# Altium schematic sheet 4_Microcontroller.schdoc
size 309 x 223 mm; Symbol: Sheet-Symbol_A4; Device: Sheet-Symbol_A4; @Project Name: ODrive Rev Motor Module; @Page Count: 5; @Update Date: 2024-10-23; @Create Date: 2024-10-18; @Schematic Name: Schematic-A; @Page No: 4; @Page Name: Microcontroller; Company: EasyEDA.com; Reviewed: EasyEDA; Version: V0.1; Page Size: A4; Part Number: JLCPCB-002; Drawn: EasyEDA; @Board Name: BaseModule; @Create Time: 18:23:50; @Update Time: 17:08:23
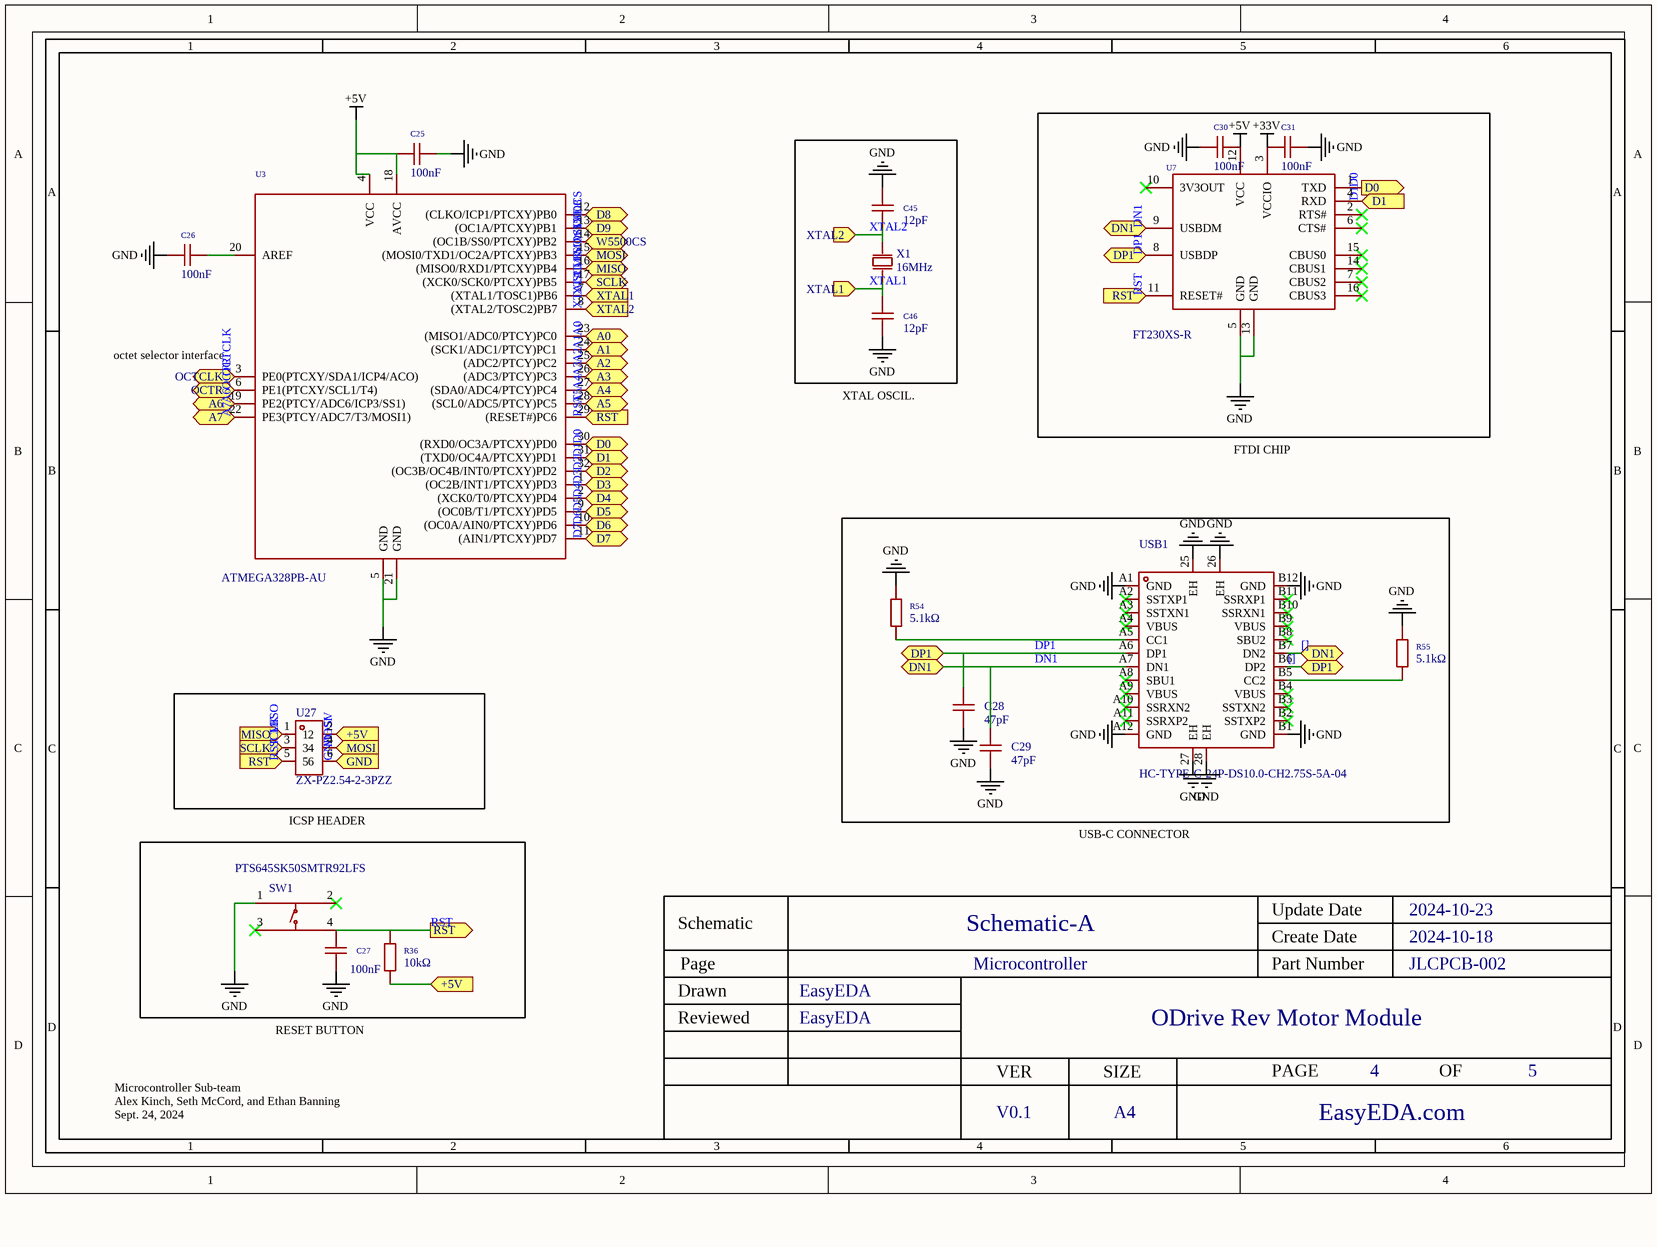
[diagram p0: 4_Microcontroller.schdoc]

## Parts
C25  100nF  [C0805]  (value not drawn)
C26  100nF  [C0805]  (value not drawn)
C27  100nF  [C0805]  (value not drawn)
C28  47pF  [C0805]  (value not drawn)
C29  47pF  [C0805]  (value not drawn)
C30  100nF  [C0805]  (value not drawn)
C31  100nF  [C0805]  (value not drawn)
C45  12pF  [C0402]  (value not drawn)
C46  12pF  [C0402]  (value not drawn)
R36  10kΩ  [R0805]  (value not drawn)
R54  5.1kΩ  [R0402]  (value not drawn)
R55  5.1kΩ  [R0402]  (value not drawn)
SW1  PTS645SK50SMTR92LFS  [KEY-SMD_4P-L6.0-W6.0-P4.50-LS9.0]  (value not drawn)
U3  ATMEGA328PB-AU  [TQFP-32_L7.0-W7.0-P0.80-LS9.0-BL]  (value not drawn)
U7  FT230XS-R  [SSOP-16_L5.0-W4.4-P0.65-LS6.4-BL]  (value not drawn)
U27  ZX-PZ2.54-2-3PZZ  [HDR-TH_6P-P2.54-V-M-R2-C3-S2.54-1]  (value not drawn)
USB1  HC-TYPE-C-24P-DS10.0-CH2.75S-5A-04  [USB-TYPE-C-SMD_HC-TYPE-C-24P-DS10.0-CH2.75S-5A-04]  (value not drawn)
X1  16MHz  [HC-49S_L11.4-W4.8]  (value not drawn)

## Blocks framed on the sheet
ICSP HEADER: C27 R36 SW1

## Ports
+5V (in), A0 (bidir), A1 (bidir), A2 (bidir), A3 (bidir), A4 (bidir), A5 (bidir), A6 (bidir), A7 (bidir), D0 (bidir), D0 (out), D1 (bidir), D1 (in), D2 (bidir), D3 (bidir), D4 (bidir), D5 (bidir), D6 (bidir), D7 (bidir), D8 (bidir), D9 (bidir), DN1 (bidir), DP1 (bidir), GND (in), MISO (bidir), MISO (in), MOSI (bidir), MOSI (in), OCTCLK (bidir), OCTR (bidir), RST (in), RST (out), SCLK (bidir), SCLK (in), W5500CS (bidir), XTAL1 (in), XTAL2 (in)

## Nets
+5V: C25.1 C30.2 R36.1 U3.4(VCC) U3.18(AVCC) U7.12(VCC) U27.2 ; port +5V
+33V: C31.1 U7.3(VCCIO)
GND: C25.2 C26.1 C27.1 C28.1 C29.1 C30.1 C31.2 C45.2 C46.1 R54.2 R55.2 SW1.1 U3.5(GND) U3.21(GND) U7.5(GND) U7.13(GND) U27.6 USB1.25(EH) USB1.26(EH) USB1.27(EH) USB1.28(EH) USB1.A1(GND) USB1.A12(GND) USB1.B1(GND) USB1.B12(GND) ; port GND
[]: C28.2 C29.2 U7.8(USBDP) U7.9(USBDM) USB1.A6(DP1) USB1.A7(DN1) USB1.B6(DP2) USB1.B7(DN2) ; port DN1, port DP1  [also labelled DN1, DP1]
A0: U3.23((MISO1/ADC0/PTCY)PC0) ; port A0
A1: U3.24((SCK1/ADC1/PTCY)PC1) ; port A1
A2: U3.25((ADC2/PTCY)PC2) ; port A2
A3: U3.26((ADC3/PTCY)PC3) ; port A3
A4: U3.27((SDA0/ADC4/PTCY)PC4) ; port A4
A5: U3.28((SCL0/ADC5/PTCY)PC5) ; port A5
A6: U3.19(PE2(PTCY/ADC6/ICP3/SS1)) ; port A6
A7: U3.22(PE3(PTCY/ADC7/T3/MOSI1)) ; port A7
D0: U3.30((RXD0/OC3A/PTCXY)PD0) U7.1(TXD) ; port D0
D1: U3.31((TXD0/OC4A/PTCXY)PD1) U7.4(RXD) ; port D1
D2: U3.32((OC3B/OC4B/INT0/PTCXY)PD2) ; port D2
D3: U3.1((OC2B/INT1/PTCXY)PD3) ; port D3
D4: U3.2((XCK0/T0/PTCXY)PD4) ; port D4
D5: U3.9((OC0B/T1/PTCXY)PD5) ; port D5
D6: U3.10((OC0A/AIN0/PTCXY)PD6) ; port D6
D7: U3.11((AIN1/PTCXY)PD7) ; port D7
D8: U3.12((CLKO/ICP1/PTCXY)PB0) ; port D8
D9: U3.13((OC1A/PTCXY)PB1) ; port D9
MISO: U3.16((MISO0/RXD1/PTCXY)PB4) U27.1 ; port MISO
MOSI: U3.15((MOSI0/TXD1/OC2A/PTCXY)PB3) U27.4 ; port MOSI
OCTCLK: U3.3(PE0(PTCXY/SDA1/ICP4/ACO)) ; port OCTCLK
OCTR: U3.6(PE1(PTCXY/SCL1/T4)) ; port OCTR
RST: C27.2 R36.2 SW1.4 U3.29((RESET#)PC6) U7.11(RESET#) U27.5 ; port RST
SCLK: U3.17((XCK0/SCK0/PTCXY)PB5) U27.3 ; port SCLK
W5500CS: U3.14((OC1B/SS0/PTCXY)PB2) ; port W5500CS
XTAL1: C46.2 U3.7((XTAL1/TOSC1)PB6) X1.1(OSC1) ; port XTAL1
XTAL2: C45.1 U3.8((XTAL2/TOSC2)PB7) X1.2(OSC2) ; port XTAL2
NetC26_2: C26.2 U3.20(AREF)
NetR54_1: R54.1 USB1.A5(CC1)
NetR55_1: R55.1 USB1.B5(CC2)

Not connected (* = marked no-connect by the designer): SW1 2* 3*; U7 2(RTS#)* 6(CTS#)* 7(CBUS2)* 10(3V3OUT)* 14(CBUS1)* 15(CBUS0)* 16(CBUS3)*; USB1 A2(SSTXP1)* A3(SSTXN1)* A4(VBUS)* A8(SBU1)* A9(VBUS)* A10(SSRXN2)* A11(SSRXP2)* B2(SSTXP2)* B3(SSTXN2)* B4(VBUS)* B8(SBU2)* B9(VBUS)* B10(SSRXN1)* B11(SSRXP1)*

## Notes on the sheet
- (near U3) octet selector interface
- XTAL OSCIL.
- FTDI CHIP
- USB-C CONNECTOR
- Microcontroller Sub-team
  Alex Kinch, Seth McCord, and Ethan Banning
  Sept. 24, 2024
- RESET BUTTON

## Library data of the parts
C25-C27 C30 C31 = 0805B104K500NT: Capacitance:100nF Tolerance:±10% Tolerance:±10% Voltage Rated: Temperature Coefficient:; Manufacturer: FH(风华); Add into BOM: yes; Tolerance: ±10%
C28 C29 = CL21C470JBANNNC: Capacitance: Tolerance:±5% Tolerance:±5% Voltage Rated: Temperature Coefficient:; Manufacturer: SAMSUNG(三星); Add into BOM: yes; Tolerance: ±5%
C45 C46 = CC0402JRNPO9BN120: Capacitance: Tolerance:±5% Tolerance:±5% Voltage Rated: Temperature Coefficient:; Manufacturer: YAGEO(国巨); Add into BOM: yes; Tolerance: ±5%
R36 = 0805W8F1002T5E: Type:Thick Film Resistors Resistance:10kΩ Tolerance:±1% Tolerance:±1% Power(Watts): Overload Voltage (Max): Temperature Coefficient:±100ppm/℃ Temperature Coefficient:±100ppm/℃ Operating Temperature Range:-55℃~+155℃ Operating Temperature Range:-55℃~+155℃; Manufacturer: UNI-ROYAL(厚声); Add into BOM: yes; Tolerance: ±1%
R54 R55 = 0402WGF5101TCE: Type:Thick Film Resistors Resistance:5.1kΩ Tolerance:±1% Tolerance:±1% Power(Watts): Overload Voltage (Max): Temperature Coefficient:±100ppm/℃ Temperature Coefficient:±100ppm/℃ Operating Temperature Range:-55℃~+155℃ Operating Temperature Range:-55℃~+155℃; Manufacturer: UNI-ROYAL(厚声); Add into BOM: yes; Tolerance: ±1%
SW1 = PTS645SK50SMTR92LFS: Circuit:SPST Actuator Style:Round Button Operating Force:260gf Mounting Style:Brick nogging Switch Length:6mm Switch Width:6mm Switch Height:1.55mm Contact Current:50mA Voltage Rating (DC):12V With Lamp:- Pin Style:Gull Wing Mechanical Life:- Operating Te; Manufacturer: C&K; Add into BOM: yes; Circuit: SPST; Operating Force: 260gf; Switch Length: 6mm; Switch Height: 1.55mm; Contact Current: 50mA; Voltage Rating (DC): 12V
U3 = ATMEGA328PB-AU: CPU Core:AVR Program Storage Size:32KB RAM Size:2KB GPIO Ports Number:27 Operating Voltage Range:1.8V~5.5V Operating Voltage Range:1.8V~5.5V CPU Maximum Speed:20MHz Program Memory Type:FLASH Operating Temperature Range:-40℃~+85℃ Operating Temperature Rang; Manufacturer: MICROCHIP(美国微芯); Add into BOM: yes; CPU Core: AVR; Program Storage Size: 32KB; RAM Size: 2KB; GPIO Ports Number: 27; CPU Maximum Speed: 20MHz; Program Memory Type: FLASH; ADC (Bit): 10bit; Watchdog: 有
U7 = FT230XS-R: Applications Function:USB转UART Protocol:UART Supply Voltage:3.3V~5V Supply Voltage:3.3V~5V Operating Temperature:-40℃~+85℃ Operating Temperature:-40℃~+85℃; Manufacturer: FTDI(飞特帝亚); Add into BOM: yes; Protocol: UART
U27 = ZX-PZ2.54-2-3PZZ: Pin Structure:2x3P Pitch:2.54mm Row Spacing:2.54mm Circluar Pins/Square Pins:Square Pins Mounting Type:Straight Number of Rows:双排 Number of Pins:6P Current Rating (Max):3A Voltage Rating (Max):1kV Length of Mating Pin:6mm Insulation Height:2.5mm Length of; Manufacturer: Megastar(兆星); Add into BOM: yes; Pin Structure: 2x3P; Pitch: 2.54mm; Current Rating (Max): 3A; Voltage Rating (Max): 1kV
USB1 = HC-TYPE-C-24P-DS10.0-CH2.75S-5A-04: Connector Type:Type-C Standard:USB 3.1 Gender:Female Mounting Style:Bend insert Number of Contacts:24P Number of Ports:1 Current Rating - Power (Max):5A Contact Material:Brass Alloy Contact Plating:Gold Operating Temperature Range:-30℃~+80℃ Operating Temp; Manufacturer: HCTL(华灿天禄); Add into BOM: yes; Connector Type: Type-C; Gender: Female; Number of Contacts: 24P; Number of Ports: 1; Current Rating - Power (Max): 5A; Soldering Temperature(Max): 260℃
X1 = X49SM16MSD2SC: Crystal Type:Surface Mount Crystal Frequency: Normal temperature Frequency Tolerance:±20ppm Normal temperature Frequency Tolerance:±20ppm External load capacitor: Frequency Stability(Full temperature range):±30ppm Frequency Stability(Full temperature rang; Manufacturer: YXC(扬兴晶振); Add into BOM: yes; Normal temperature Frequency Tolerance: ±20ppm; Frequency Stability(Full temperature range): ±30ppm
